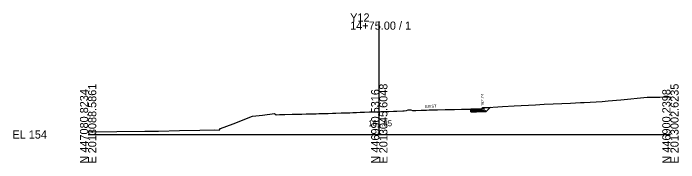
# Model space of a CAD drawing. Extents: x -26 to 1203, y -10 to 9542.
# Drawn here: x -25.7 to 202.8, y 9490.3 to 9541.7 of the extents above; entities that cross this region are included whole.
import ezdxf

# ---------------------------------------------------------------- set-up
doc = ezdxf.new("R2010")
doc.units = 0
for name, color, linetype in [('Default', 7, 'Continuous'), ('Exist Cross Section Cell', 7, 'Continuous'), ('Exist XS Center Line Elevation Label', 7, 'Continuous'), ('Exist XS Ground Line', 7, 'Continuous'), ('Prop CMT Conc Surface', 7, 'Continuous'), ('Prop CMT Concrete Structures', 7, 'Continuous'), ('Prop CMT Pvmt Course 1', 7, 'Continuous'), ('Prop CMT Pvmt Course 1 CG', 7, 'Continuous'), ('Prop CMT Pvmt Course 2', 7, 'Continuous'), ('Prop CMT Pvmt Course 3', 7, 'Continuous'), ('Prop CMT Pvmt Surface', 7, 'Continuous'), ('Prop CMT Slope Grass', 7, 'Continuous'), ('Prop CMT Subgrade Earthwork', 7, 'Continuous'), ('Prop XS Earthwork Shape', 7, 'Continuous'), ('Prop XS Hydro Elevations', 7, 'Continuous'), ('Prop XS SE Text', 7, 'Continuous')]:
    doc.layers.add(name, color=color, linetype=linetype)

msp = doc.modelspace()

# ---------------------------------------------------------------- linework, layer by layer
at = {"layer": 'Exist Cross Section Cell'}
for p, q in [((100, 9500), (100, 9538.83)), ((0, 9500), (100, 9500)), ((100, 9500), (200, 9500))]:
    msp.add_line(p, q, dxfattribs=at)
at = {"layer": 'Exist XS Ground Line'}
msp.add_lwpolyline([(0, 9500.87), (9.88, 9500.98), (19.5, 9501.13), (23.84, 9501.12), (24.17, 9501.12), (31.34, 9501.33), (38.38, 9501.49), (43.46, 9501.61), (44.97, 9501.52), (45.46, 9502.02), (49.86, 9503.7), (56.5, 9506.26), (59.88, 9506.67), (64.02, 9507.23), (64.54, 9506.81), (65.7, 9506.83), (66.56, 9506.84), (67.61, 9506.89), (70.08, 9506.96), (71.14, 9506.99), (73.02, 9507.04), (73.44, 9507.05), (74.9, 9507.08), (75.62, 9507.09), (76.43, 9507.1), (77.36, 9507.12), (78.38, 9507.14), (79.26, 9507.17), (80.54, 9507.21), (81.16, 9507.23), (82.42, 9507.27), (83.92, 9507.31), (85.08, 9507.34), (86.9, 9507.4), (87.85, 9507.42), (89.44, 9507.48), (89.91, 9507.49), (90.89, 9507.53), (92.2, 9507.59), (93.39, 9507.64), (94.96, 9507.71), (96.69, 9507.76), (97.74, 9507.8), (98.59, 9507.82), (100, 9507.85), (100.51, 9507.87), (102.48, 9507.93), (103.26, 9507.95), (104.88, 9508), (106.02, 9508.04), (108.15, 9508.11), (108.6, 9508.13), (109.36, 9508.24), (109.96, 9508.54), (110.3, 9508.54), (110.83, 9508.54), (111.43, 9508.24), (112.21, 9508.29), (112.52, 9508.3), (114.37, 9508.35), (116.19, 9508.4), (117.15, 9508.43), (118.07, 9508.45), (120.01, 9508.51), (122.62, 9508.58), (125.79, 9508.62), (128.19, 9508.66), (130.39, 9508.69), (130.96, 9508.7), (131.51, 9508.71), (133, 9508.74), (133.41, 9508.75), (134.84, 9508.77), (135.19, 9508.78), (135.83, 9509.19), (142.31, 9509.59), (146.32, 9509.81), (153.63, 9510.24), (156.62, 9510.38), (159.69, 9510.52), (165.7, 9510.81), (169.14, 9510.97), (170.37, 9511.03), (176.5, 9511.33), (178.6, 9511.55), (182.99, 9511.94), (191.98, 9512.81), (196.37, 9512.81), (200, 9512.94)], dxfattribs=at)
at = {"layer": 'Prop CMT Conc Surface'}
msp.add_lwpolyline([(133.41, 9508.75), (135.41, 9508.74), (135.42, 9509.24), (135.92, 9509.24)], dxfattribs=at)
at = {"layer": 'Prop CMT Concrete Structures'}
for points in [[(133.41, 9508.75), (135.41, 9508.74), (135.42, 9509.24), (135.92, 9509.24)], [(135.92, 9509.24), (135.91, 9508.25), (133.41, 9508.17)], [(133.41, 9508.17), (133.41, 9508.75)]]:
    msp.add_lwpolyline(points, dxfattribs=at)
at = {"layer": 'Prop CMT Pvmt Course 1'}
for points in [[(131.4, 9508.69), (133.41, 9508.75)], [(131.4, 9508.69), (131.4, 9508.69)], [(131.4, 9508.44), (131.4, 9508.69)], [(133.41, 9508.5), (131.4, 9508.44)], [(133.41, 9508.75), (133.41, 9508.5)]]:
    msp.add_lwpolyline(points, dxfattribs=at)
at = {"layer": 'Prop CMT Pvmt Course 1 CG'}
for points in [[(133.41, 9508.17), (136.41, 9508.26), (136.74, 9507.94)], [(133.41, 9507.83), (133.41, 9508.17)], [(136.74, 9507.94), (133.41, 9507.83)]]:
    msp.add_lwpolyline(points, dxfattribs=at)
at = {"layer": 'Prop CMT Pvmt Course 2'}
for points in [[(131.4, 9508.44), (133.41, 9508.5)], [(131.4, 9508.1), (131.4, 9508.44)], [(133.41, 9508.17), (131.4, 9508.1)], [(133.41, 9508.5), (133.41, 9508.17)]]:
    msp.add_lwpolyline(points, dxfattribs=at)
at = {"layer": 'Prop CMT Pvmt Course 3'}
for points in [[(131.4, 9508.1), (133.41, 9508.17)], [(131.4, 9507.77), (131.4, 9508.1)], [(133.41, 9507.83), (131.4, 9507.77)], [(133.41, 9508.17), (133.41, 9507.83)]]:
    msp.add_lwpolyline(points, dxfattribs=at)
at = {"layer": 'Prop CMT Pvmt Surface'}
msp.add_lwpolyline([(131.4, 9508.69), (133.41, 9508.75)], dxfattribs=at)
at = {"layer": 'Prop CMT Slope Grass'}
msp.add_lwpolyline([(135.92, 9509.24), (138.13, 9509.33)], dxfattribs=at)
at = {"layer": 'Prop CMT Subgrade Earthwork'}
for points in [[(133.41, 9507.83), (136.74, 9507.94), (138.13, 9509.33)], [(131.4, 9507.77), (131.4, 9508.71)], [(131.4, 9507.77), (133.41, 9507.83)], [(133.41, 9507.83), (131.4, 9507.77)]]:
    msp.add_lwpolyline(points, dxfattribs=at)
at = {"layer": 'Prop XS Earthwork Shape'}
msp.add_lwpolyline([(131.4, 9508.71), (131.4, 9507.77), (136.74, 9507.94), (138.13, 9509.33), (135.83, 9509.19), (135.19, 9508.78)], close=True, dxfattribs=at)

# ---------------------------------------------------------------- texts
at = {"layer": 'Default'}
msp.add_text('-', height=0.0001, dxfattribs=at).set_placement((0, 9500))
at = {"layer": 'Exist Cross Section Cell'}
for s, p in [('Y12', (90, 9538.83)), ('14+75.00 / 1', (90, 9536.03)), ('EL 154', (-26, 9498.6))]:
    msp.add_text(s, height=2.8, dxfattribs=at).set_placement(p)
for s, p in [('E 2013088.5861', (2.8, 9490)), ('E 2013045.6048', (102.8, 9490)), ('E 2013002.6235', (202.8, 9490)), ('N 447080.8234', (0, 9490)), ('N 446990.5316', (100, 9490)), ('N 446900.2398', (200, 9490))]:
    msp.add_text(s, height=2.8, rotation=90, dxfattribs=at).set_placement(p)
at = {"layer": 'Exist XS Center Line Elevation Label'}
msp.add_text('161.85', height=2, dxfattribs=at).set_placement((96.22, 9502.85))
at = {"layer": 'Prop XS Hydro Elevations'}
msp.add_text('162.74', height=1, rotation=90, dxfattribs=at).set_placement((135.91, 9509.74))
at = {"layer": 'Prop XS SE Text'}
msp.add_text('EXIST', height=1, rotation=1.8605, dxfattribs=at).set_placement((115.71, 9509.12))

doc.saveas('drawing.dxf')
